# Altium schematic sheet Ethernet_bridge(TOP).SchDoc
size 900 x 699 mm; SheetNumber: 1; SheetTotal: 1; SPICEModelCacheNLVBOJOE: <root> / <DocumentId>NLVBOJOE</DocumentId> / <CacheFrame Number="0"> / <Model Name="5848_744774033_3.3u" Kind="CKT"> / <Text>******* / .subckt 5848_744774033_3.3u 1 2 / Rp 1 2 12000 / Cp 1 2 3.4p / Rs 1 N3 0.042 / L1 N3 2 3.3u / .ends 5848_744774033_3.3u</Text> / </Model> / </CacheFrame> / </root>
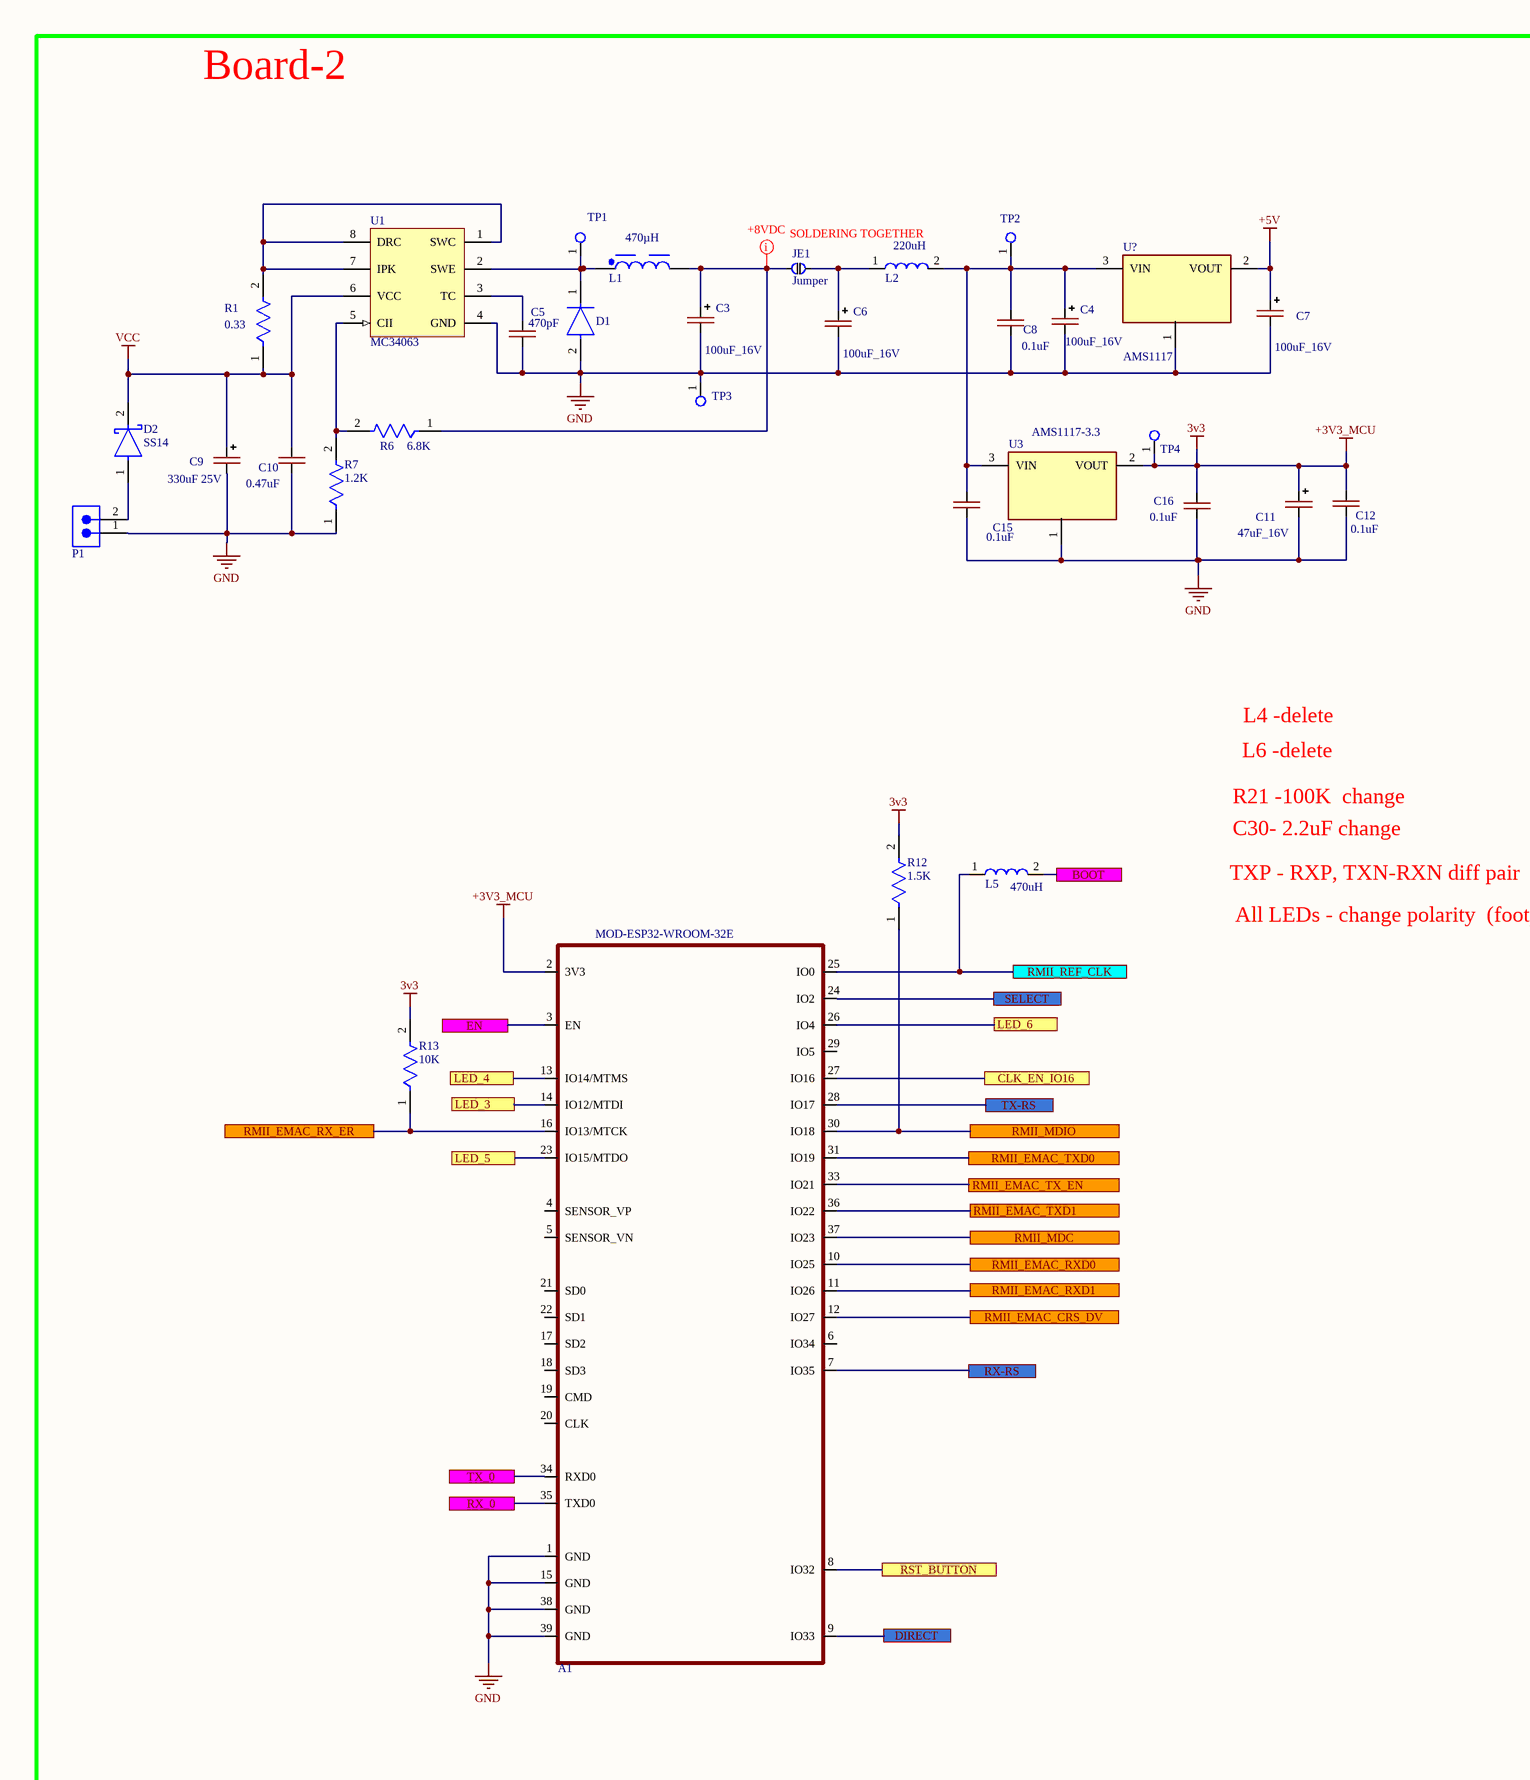
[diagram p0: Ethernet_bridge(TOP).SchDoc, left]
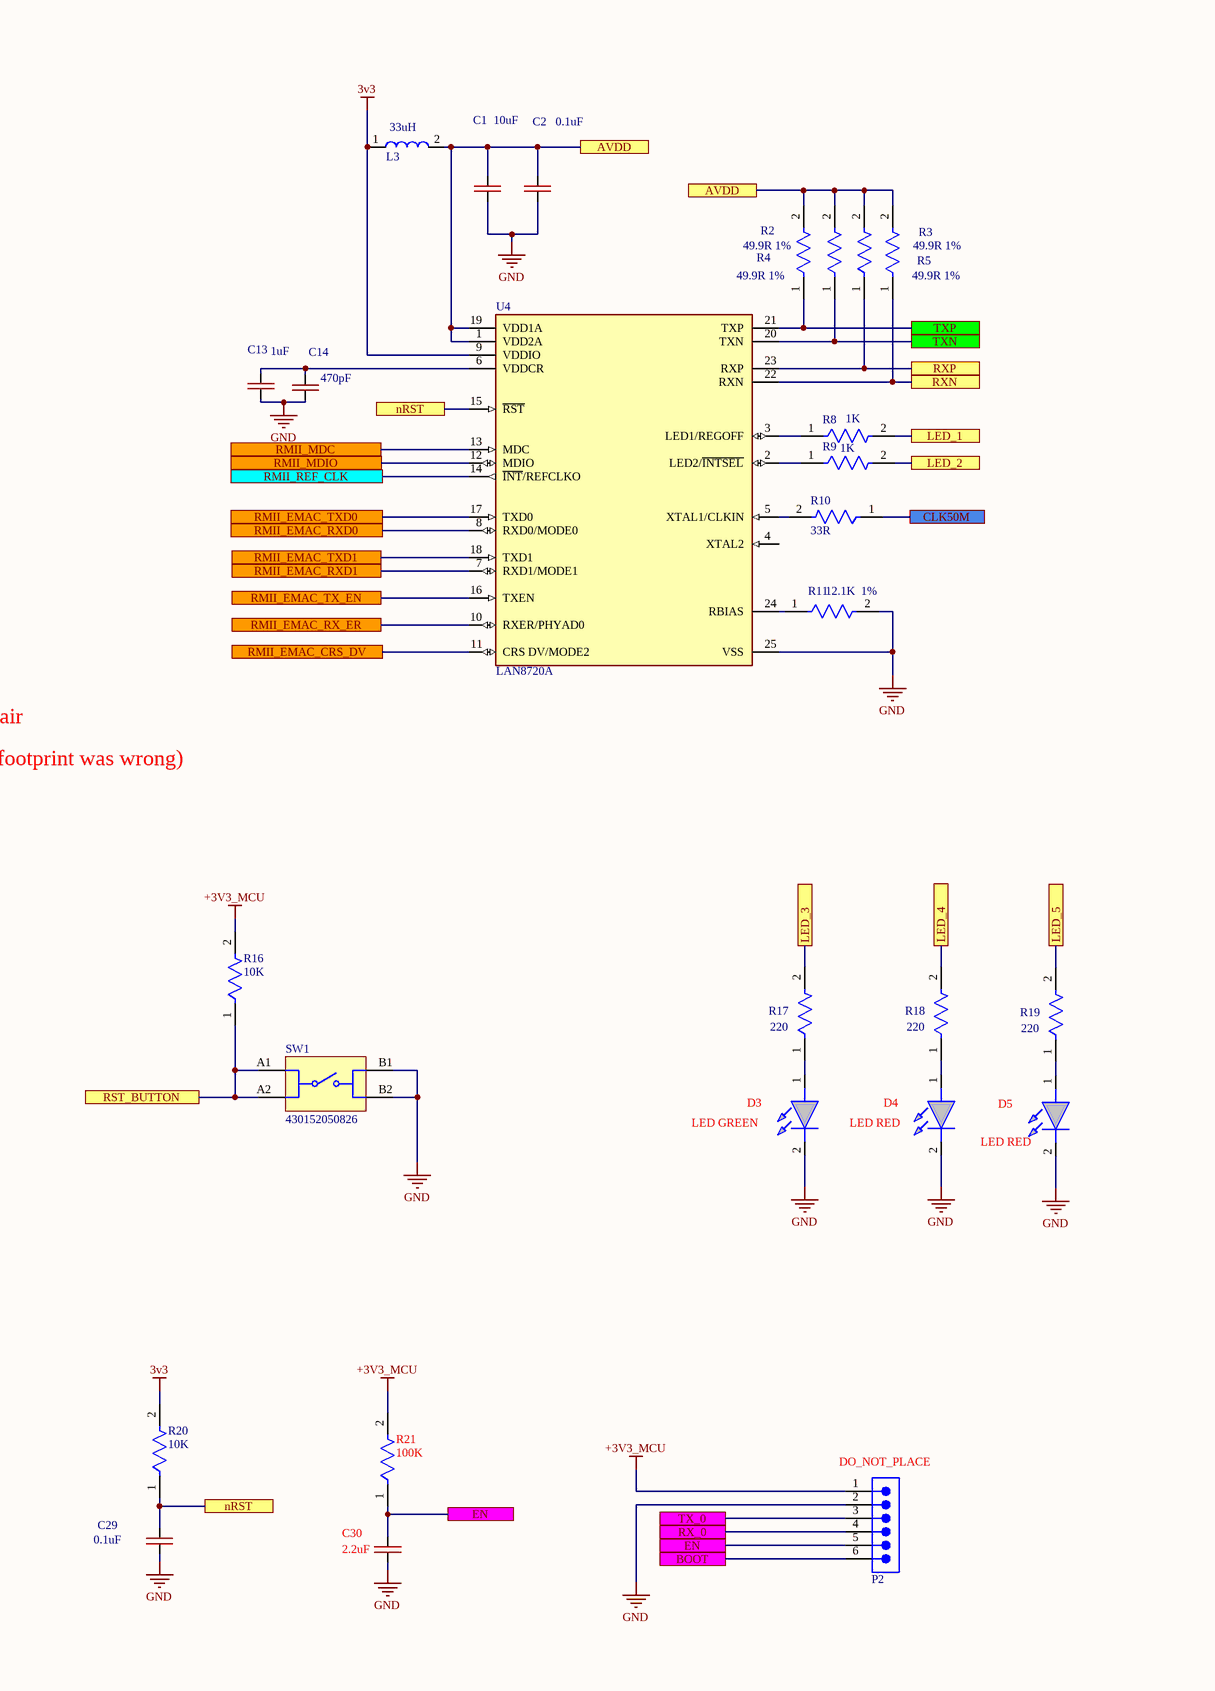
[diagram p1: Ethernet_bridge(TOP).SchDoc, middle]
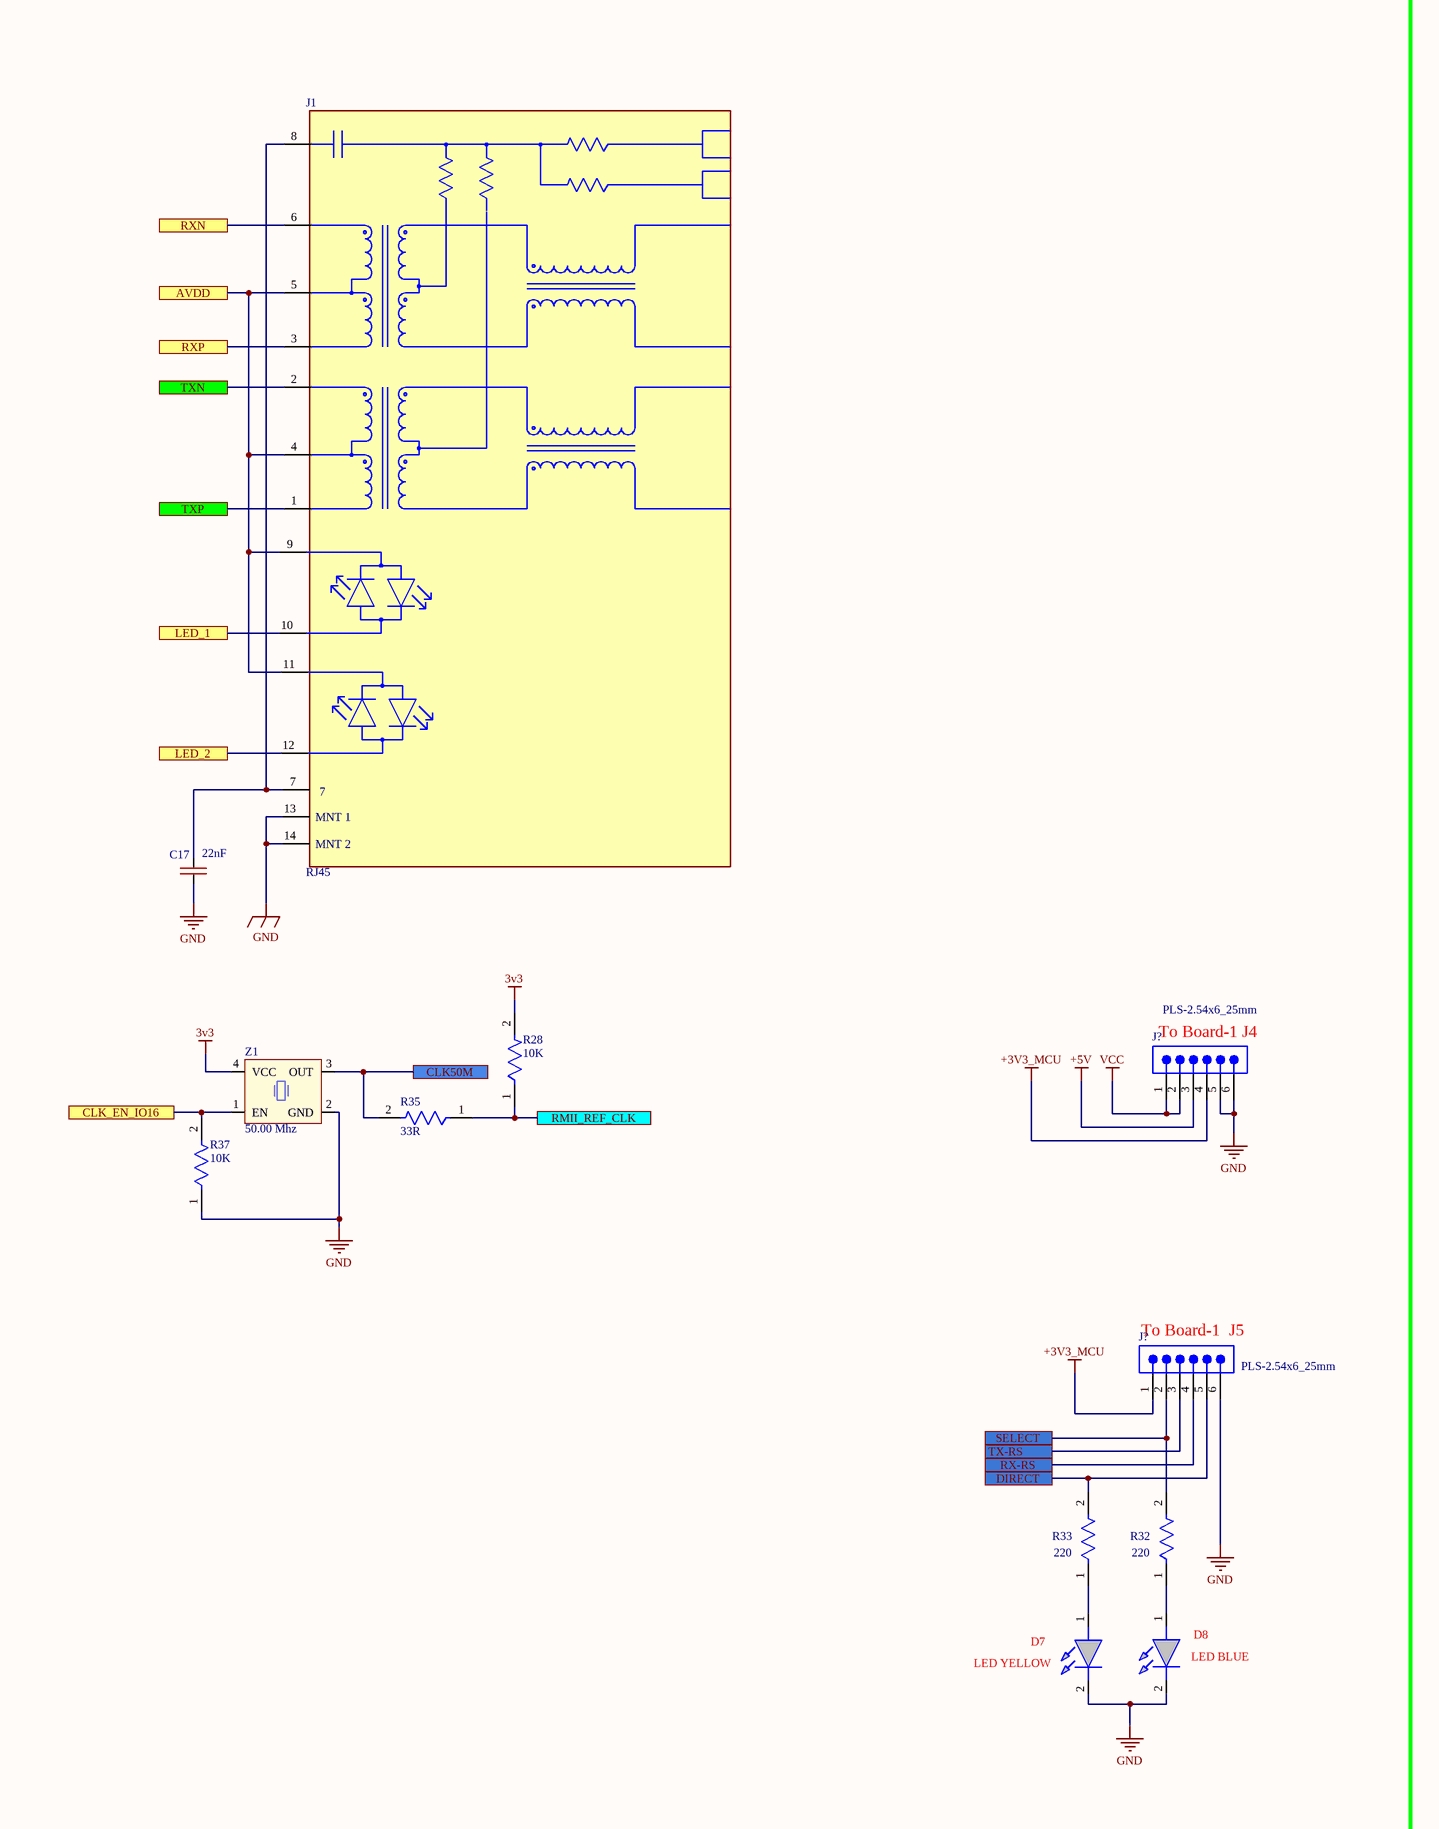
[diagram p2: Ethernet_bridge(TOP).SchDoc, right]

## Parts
(Parts that share a designator on the sheet are numbered #1, #2 ... from top to bottom, then left to right.)
A1  MOD-ESP32-WROOM-32E  [MOD-ESP32-WROOM-32E]
C1  10uF  [CAP-0805]
C2  0.1uF  [CAP-0805]
C3  100uF_16V  [CAP-TAN-D]
C4  100uF_16V  [CAP-TAN-D]
C5  470pF  [CAP-0603]
C6  100uF_16V  [CAP-TAN-D]
C7  100uF_16V  [CAP-TAN-D]
C8  0.1uF  [CAP-0603]
C9  330uF 25V  [CAP_SMD_Size_E]
C10  0.47uF  [CAP-0805]
C11  47uF_16V  [CAP-TAN-D]
C12  0.1uF  [CAP-0603]
C13  1uF  [CAP-0603]
C14  470pF  [CAP-0603]
C15  0.1uF  [CAP-0603]
C16  0.1uF  [CAP-0603]
C17  22nF  [CAP-0603]
C29  0.1uF  [CAP-0603]
C30  2.2uF  [CAP-0603]
D1  ES1G  [FP-403AE-MFG]  (value not drawn)
D2  SS14  [DO-214-AC]
D3  LED GREEN  [LED_GREEN]
D4  LED RED  [LED_RED]
D5  LED RED  [LED_RED]
D7  LED YELLOW  [LED_YELLOW]
D8  LED BLUE  [LED_BLUE]
J1  RJ45  [RJ-45]
J?#1  PLS-2.54x6_25mm  [PLS2.54x25mm]
J?#2  PLS-2.54x6_25mm  [PLS2.54x25mm]
JE1  Jumper  [JE]
L1  470µH  [WE-PD2_5848]
L2  220uH  [Coil_4.5x4.5_mm]
L3  33uH  [Coil_4.5x4.5_mm]
L5  470uH  [Coil_4.5x4.5_mm]
P1  691305540002  [691305540002]  (value not drawn)
P2  61300611121  [61300611121]  (value not drawn)
R1  0.33  [RES-1206]
R2  49.9R 1%  [RES-0603]
R3  49.9R 1%  [RES-0603]
R4  49.9R 1%  [RES-0603]
R5  49.9R 1%  [RES-0603]
R6  6.8K  [RES-0805]
R7  1.2K  [RES-0805]
R8  1K  [RES-0603]
R9  1K  [RES-0603]
R10  33R  [RES-0603]
R11  12.1K  1%  [RES-0603]
R12  1.5K  [RES-0603]
R13  10K  [RES-0603]
R16  10K  [RES-0603]
R17  220  [RES-0603]
R18  220  [RES-0603]
R19  220  [RES-0603]
R20  10K  [RES-0603]
R21  100K  [RES-0603]
R28  10K  [RES-0603]
R32  220  [RES-0603]
R33  220  [RES-0603]
R35  33R  [RES-0603]
R37  10K  [RES-0603]
SW1  430152050826  [430152050826]
TP1  Test_Point_PCB  [Test_Point]  (value not drawn)
TP2  Test_Point_PCB  [Test_Point]  (value not drawn)
TP3  Test_Point_PCB  [Pin_Test_Point(Orange)]  (value not drawn)
TP4  Test_Point_PCB  [Test_Point]  (value not drawn)
U1  MC34063  [SOIC-8_M]
U3  AMS1117-3.3  [SOT-89]
U4  LAN8720A  [24QFN-4x4B-IPC_A]
U?  AMS1117  [SOT-89]
Z1  50.00 Mhz  [50.00Mhz active quartz]

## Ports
AVDD (see Ethernet_bridge(TOP)[3A]), AVDD (see Ethernet_bridge(TOP)[3A], Ethernet_bridge(TOP)[4A]), BOOT (see Ethernet_bridge(TOP)[2B]), BOOT (see Ethernet_bridge(TOP)[3C]), CLK50M (see Ethernet_bridge(TOP)[4B]), CLK50M (see Ethernet_bridge(TOP)[5B]), CLK_EN_IO16 (see Ethernet_bridge(TOP)[2B]), CLK_EN_IO16 (see Ethernet_bridge(TOP)[4B]), DIRECT (see Ethernet_bridge(TOP)[2C]), DIRECT (see Ethernet_bridge(TOP)[5C]), EN (see Ethernet_bridge(TOP)[1B], Ethernet_bridge(TOP)[3C]), EN (see Ethernet_bridge(TOP)[3C]), LED_1 (see Ethernet_bridge(TOP)[4A]), LED_1 (see Ethernet_bridge(TOP)[4B]), LED_2 (see Ethernet_bridge(TOP)[4B]), LED_3 (see Ethernet_bridge(TOP)[1B]), LED_3 (see Ethernet_bridge(TOP)[3B]), LED_4 (see Ethernet_bridge(TOP)[1B]), LED_4 (see Ethernet_bridge(TOP)[4B]), LED_5 (see Ethernet_bridge(TOP)[1B]), LED_5 (see Ethernet_bridge(TOP)[4B]), LED_6, nRST (see Ethernet_bridge(TOP)[3A]), nRST (see Ethernet_bridge(TOP)[3C]), RMII_EMAC_CRS_DV (see Ethernet_bridge(TOP)[2B]), RMII_EMAC_CRS_DV (see Ethernet_bridge(TOP)[3B]), RMII_EMAC_RX_ER (see Ethernet_bridge(TOP)[1B]), RMII_EMAC_RX_ER (see Ethernet_bridge(TOP)[3B]), RMII_EMAC_RXD0 (see Ethernet_bridge(TOP)[2B]), RMII_EMAC_RXD0 (see Ethernet_bridge(TOP)[3B]), RMII_EMAC_RXD1 (see Ethernet_bridge(TOP)[2B]), RMII_EMAC_RXD1 (see Ethernet_bridge(TOP)[3B]), RMII_EMAC_TX_EN (see Ethernet_bridge(TOP)[2B]), RMII_EMAC_TX_EN (see Ethernet_bridge(TOP)[3B]), RMII_EMAC_TXD0 (see Ethernet_bridge(TOP)[2B]), RMII_EMAC_TXD0 (see Ethernet_bridge(TOP)[3B]), RMII_EMAC_TXD1 (see Ethernet_bridge(TOP)[2B]), RMII_EMAC_TXD1 (see Ethernet_bridge(TOP)[3B]), RMII_MDC (see Ethernet_bridge(TOP)[2B]), RMII_MDC (see Ethernet_bridge(TOP)[3A]), RMII_MDIO (see Ethernet_bridge(TOP)[2B]), RMII_MDIO (see Ethernet_bridge(TOP)[3B]), RMII_REF_CLK (see Ethernet_bridge(TOP)[2B], Ethernet_bridge(TOP)[3B]), RMII_REF_CLK (see Ethernet_bridge(TOP)[2B], Ethernet_bridge(TOP)[5B]), RMII_REF_CLK (see Ethernet_bridge(TOP)[3B], Ethernet_bridge(TOP)[5B]), RST_BUTTON (see Ethernet_bridge(TOP)[2C]), RST_BUTTON (see Ethernet_bridge(TOP)[3B]), RX-RS (see Ethernet_bridge(TOP)[2B]), RX-RS (see Ethernet_bridge(TOP)[5C]), RX_0 (see Ethernet_bridge(TOP)[1B]), RX_0 (see Ethernet_bridge(TOP)[3C]), RXN (see Ethernet_bridge(TOP)[4A]), RXP (see Ethernet_bridge(TOP)[4A]), SELECT (see Ethernet_bridge(TOP)[2B]), SELECT (see Ethernet_bridge(TOP)[5C]), TX-RS (see Ethernet_bridge(TOP)[2B]), TX-RS (see Ethernet_bridge(TOP)[5C]), TX_0 (see Ethernet_bridge(TOP)[1B]), TX_0 (see Ethernet_bridge(TOP)[3C]), TXN (see Ethernet_bridge(TOP)[4A]), TXP (see Ethernet_bridge(TOP)[4A]), TXP (see Ethernet_bridge(TOP)[4B])

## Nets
+3V3_MCU: A1.2(3V3) C11.1(+) C12.2 C16.2 J?#1.4 J?#2.1 L3.1 P2.1 R12.2 R13.2 R16.2 R20.2 R21.2 R28.2 TP4.1(G9) U3.2(VOUT) U4.9(VDDIO) Z1.4(VCC)  [also labelled 3v3]
+5V: C7.1(+) J?#1.3 U?.2(VOUT)
GND: A1.1(GND) A1.15(GND) A1.38(GND) A1.39(GND) C1.1 C2.1 C3.2(-) C4.2(-) C5.2 C6.2(-) C7.2(-) C8.1 C9.2(-) C10.2 C11.2(-) C12.1 C13.1 C14.1 C15.1 C16.1 C17.1 C29.1 C30.1 D1.2(A) D3.2(K) D4.2(K) D5.2(K) D7.2(K) D8.2(K) J1.13(MNT_1) J1.14(MNT_2) J?#1.5 J?#1.6 J?#2.6 P1.1 P2.2 R7.1 R11.2 R37.1 SW1.B1 SW1.B2 TP3.1(G9) U1.4(GND) U3.1(Ground) U4.25(VSS) U?.1(Ground) Z1.2(GND)
VCC: C9.1(+) C10.1 D2.2(C) J?#1.1 J?#1.2 R1.1 U1.6(VCC)
AVDD: C1.2 C2.2 J1.4 J1.5 J1.9(2_ANODE_YELLOW/CATHODE_GREEN) J1.11(2_ANODE_YELLOW/CATHODE_GREEN) L3.2 R2.2 R3.2 R4.2 R5.2 U4.1(VDD2A) U4.19(VDD1A) ; port AVDD
BOOT: L5.2 P2.6 ; port BOOT
CLK50M: R10.1 R35.2 Z1.3(OUT) ; port CLK50M
CLK_EN_IO16: A1.27(IO16) R37.2 Z1.1(EN) ; port CLK_EN_IO16
DIRECT: A1.9(IO33) J?#2.5 R33.2 ; port DIRECT
EN: A1.3(EN) C30.2 P2.5 R21.1 ; port EN
LED_1: J1.10(2_CATHODE_YELLOW/ANODE_GREEN) R8.2 ; port LED_1
LED_2: J1.12(2_CATHODE_YELLOW/ANODE_GREEN) R9.2 ; port LED_2
LED_3: A1.14(IO12/MTDI) R17.2 ; port LED_3
LED_4: A1.13(IO14/MTMS) R18.2 ; port LED_4
LED_5: A1.23(IO15/MTDO) R19.2 ; port LED_5
LED_6: A1.26(IO4) ; port LED_6
nRST: C29.2 R20.1 U4.15(~{RST}) ; port nRST
RMII_EMAC_CRS_DV: A1.12(IO27) U4.11(CRS_DV/MODE2) ; port RMII_EMAC_CRS_DV
RMII_EMAC_RX_ER: A1.16(IO13/MTCK) R13.1 U4.10(RXER/PHYAD0) ; port RMII_EMAC_RX_ER
RMII_EMAC_RXD0: A1.10(IO25) U4.8(RXD0/MODE0) ; port RMII_EMAC_RXD0
RMII_EMAC_RXD1: A1.11(IO26) U4.7(RXD1/MODE1) ; port RMII_EMAC_RXD1
RMII_EMAC_TX_EN: A1.33(IO21) U4.16(TXEN) ; port RMII_EMAC_TX_EN
RMII_EMAC_TXD0: A1.31(IO19) U4.17(TXD0) ; port RMII_EMAC_TXD0
RMII_EMAC_TXD1: A1.36(IO22) U4.18(TXD1) ; port RMII_EMAC_TXD1
RMII_MDC: A1.37(IO23) U4.13(MDC) ; port RMII_MDC
RMII_MDIO: A1.30(IO18) R12.1 U4.12(MDIO) ; port RMII_MDIO
RMII_REF_CLK: A1.25(IO0) L5.1 R28.1 R35.1 U4.14(~{INT}/REFCLKO) ; port RMII_REF_CLK
RST_BUTTON: A1.8(IO32) R16.1 SW1.A1 SW1.A2 ; port RST_BUTTON
RX-RS: A1.7(IO35) J?#2.4 ; port RX-RS
RX_0: A1.35(TXD0) P2.4 ; port RX_0
RXN: J1.6 R5.1 U4.22(RXN) ; port RXN
RXP: J1.3 R3.1 U4.23(RXP) ; port RXP
SELECT: A1.24(IO2) J?#2.2 R32.2 ; port SELECT
TX-RS: A1.28(IO17) J?#2.3 ; port TX-RS
TX_0: A1.34(RXD0) P2.3 ; port TX_0
TXN: J1.2 R4.1 U4.20(TXN) ; port TXN
TXP: J1.1 R2.1 U4.21(TXP) ; port TXP
NetC3_1: C3.1(+) JE1.2 L1.2 R6.1
NetC4_1: C4.1(+) C8.2 C15.2 L2.2 TP2.1(G9) U3.3(VIN) U?.3(VIN)
NetC5_1: C5.1 U1.3(TC)
NetC6_1: C6.1(+) JE1.1 L2.1
NetC13_2: C13.2 C14.2 U4.6(VDDCR)
NetC17_2: C17.2 J1.7 J1.8
NetD1_1: D1.1(C) L1.1 TP1.1(G9) U1.2(SWE)
NetD2_1: D2.1(A) P1.2
NetD3_1: D3.1(A) R17.1
NetD4_1: D4.1(A) R18.1
NetD5_1: D5.1(A) R19.1
NetD7_1: D7.1(A) R33.1
NetD8_1: D8.1(A) R32.1
NetR1_2: R1.2 U1.1(SWC) U1.7(IPK) U1.8(DRC)
NetR6_2: R6.2 R7.2 U1.5(CII)
NetR8_1: R8.1 U4.3(LED1/REGOFF)
NetR9_1: R9.1 U4.2(LED2/~{INTSEL})
NetR10_2: R10.2 U4.5(XTAL1/CLKIN)
NetR11_1: R11.1 U4.24(RBIAS)

Not connected (* = marked no-connect by the designer): A1 4(SENSOR_VP) 5(SENSOR_VN) 6(IO34) 17(SD2) 18(SD3) 19(CMD) 20(CLK) 21(SD0) 22(SD1) 29(IO5); U4 4(XTAL2)

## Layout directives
mark named +8VDC: (no net found under the mark)

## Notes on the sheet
- Board-2
- SOLDERING TOGETHER
- L4 -delete
- L6 -delete
- R21 -100K  change
- C30- 2.2uF change
- TXP - RXP, TXN-RXN diff pair
- All LEDs - change polarity  (footprint was wrong)
- (near J?#1) To Board-1 J4
- (near J?#2) To Board-1  J5
- (near P2) DO_NOT_PLACE

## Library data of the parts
C1 C2 C5 C8 C10 C12-C17 C29 C30 = CAP-NON-POLAR
C3 C4 C6 C7 C9 = CAP_POL_SMD
C11 = CAP-POLAR
D1 = ES1G: Ultrafast
D3-D5 D7 D8 = LED: WURTH ELEKTRONIK - 151031YS06000 - LED, Yellow, Through Hole, T-1 (3mm), 30 mA, 2 V, 590 nm; Geometry.Height: 5.5mm
J1 = HRK1-1B72F09
JE1 = JE
L1 = 744774033: WE-PD2 SMT Power Inductor, size 5848, 3.3µH, 4A, 0.06Ω; Manufacturer: Wurth Elektronik; Case/Size Code: 5848; DC Resistance: 0.042Ω; Saturation Current: 7.5A; Self Resonant Frequency: 43MHz
L2 L3 L5 = Coil
P1 = 691305540002: WR-TBL Series 3055 PCB Header Horizontal Entry with Plastic Latches, THT, pitch 5.08mm, 2p; Manufacturer: Wurth Elektronik; Modularity: No; Rated Current: 16A; Working Voltage: 300V
P2 = 61300611121: WR-PHD Pin Header, THT, Vertical, pitch 2.54mm, 1 Row, 6P; Manufacturer: Wurth Elektronik; Contact Resistance: 20mΩ; Rated Current: 3A; Working Voltage: 250V; Withstanding Voltage: 500V
R1-R10 R12 R13 R16-R20 R28 R32 R33 R35 R37 = RES-CONST
R11 = RES-CONST: 12.1K
R21 = RES-CONST: 10K
SW1 = 430152050826: WS-TASV SMT Tact Switch, 6mm x 6mm, 260gf, SPST-NO, 12V, 50mA; Manufacturer: Wurth Elektronik; Washable: No
TP1-TP4 = TP_PCB?: Test_Point
U3 = AMS1117
U4 = LAN7820A
Z1 = Crystal_50Mhz_active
